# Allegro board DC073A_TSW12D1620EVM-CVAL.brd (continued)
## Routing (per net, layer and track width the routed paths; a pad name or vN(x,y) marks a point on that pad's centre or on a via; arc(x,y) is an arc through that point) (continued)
N21623803: length 2.1
  BOTTOM w0.152: U12.52 30.7,37.88 R192.1
N21623805: length 2.7
  BOTTOM w0.152: R191.1 28.54,37.85 29.7,39 U12.54
N21623807: length 3.2
  BOTTOM w0.152: U12.48 36.26,41.84 R193.1
N21623845: length 2.4
  BOTTOM w0.152: R155.1 30.2,38.45 U12.53
N21637810:
  vias: v2(14.61,98.55)
N21637823: length 2
  BOTTOM w0.254: U20.1 16.19,99.12 R188.1
N21637881: length 39.5
  L10_SIG3 w0.127: SW1.2 6.68,131.5 10.29,127.89 10.29,124.28 10.76,123.81 10.76,111.87 10.36,111.48 10.36,101.32 12.19,99.49 v1(15.44,99.49)
  BOTTOM w0.152: v1(15.44,99.49) 15.69,99.74 U20.2
N21638540: length 10.1
  BOTTOM w0.152: U20.9 12.19,94.04 J35.1
N21638545: length 80
  TOP w0.305: v1(23.57,90.3) 18.47,90.3 J35.2 17.42,95.35 TP17.1
  BOTTOM w0.305: v1(23.57,90.3) 28.13,90.3 28.15,90.32 28.59,90.32 28.62,90.3 28.65,90.3 39.67,79.27 39.67,78.18 42.7,75.16 47.52,75.16 49.05,73.63 62.99,73.63 63.45,73.18 67.34,73.18 70.03,70.48 U22.2
N21638708: length 18.2
  BOTTOM w0.152: JP13.1 11.19,87.24 U20.11
N21638717: length 14
  BOTTOM w0.152: U20.10 11.69,90.68 JP12.1
N21648189: length 11.6
  BOTTOM w0.305: TP18.1 25.73,88.72 25.43,89.03 U21.1 18.72,89.03 JP12.2
N21648194: length 78.4
  BOTTOM w0.305: JP13.2 17.3,83.54 19.1,81.74 29.77,81.74 38.43,73.08 47.27,73.08 48.74,71.6 52.81,71.6 55.78,68.63 59.13,68.63 62.23,71.73 67.08,71.73 69.55,69.27 84.07,69.27 84.12,69.22 TP19.1
N21648707: length 5
  TOP w0.305: 16.71,100.94 16.71,100.74 v2(16.92,100.53) 17.07,100.69 17.39,100.69 17.65,100.95 17.65,101.02 v4(17.86,101.02) ; 16.71,100.94 17.78,100.94 v4(17.86,101.02) ; 16.71,100.94 v4(16.71,101.14) v4(17.2,101.14) 17.73,101.14 v4(17.86,101.02)
  BOTTOM w0.305: v4(17.2,101.14) 17.73,101.14 v4(17.86,101.02)
N21648712: length 3.5
  TOP w0.305: v4(17.86,101.63) 17.83,101.65 v4(17.2,101.65) v4(16.71,101.65) ; v4(17.22,103.15) 17.07,103 R186.2 16.87,103 v4(16.71,103.15)
  BOTTOM w0.305: v4(17.86,101.63) 17.22,101.63 v4(17.2,101.65)
  BOTTOM w0.508: v2(19.43,102.95) v2(19.43,101.91)
N21649143: length 7
  BOTTOM w0.305: U20.46 18.01,102.14 19.25,100.89 C231.1 19.97,100.89 22.31,103.23 Y3.1
N21649147: length 6.9
  BOTTOM w0.305: U20.45 17.9,102.64 19.23,103.96 C232.1 19.46,103.96 20.41,103.01 20.84,103.01 21.96,104.13 Y3.2
N21650021: length 8.3
  TOP w0.381: Y4.2 24.08,106.35 C235.1 20.4,106.35 19.96,105.92 18.54,105.92 v4(16.76,104.14)
N21650025: length 8.5
  TOP w0.381: v4(16.99,103.66) 17.45,103.66 18.47,102.64 18.47,102.03 19.28,101.22 C234.1 24.08,101.22 Y4.1
N21650057: length 6.8
  TOP w0.381: C234.2 20.7,102.26 v1(20.7,104.62) C235.2
  BOTTOM w0.305: U20.41 20.51,104.64 v1(20.7,104.62)
N216554902: length 20.8
  L05_SIG1 w0.127: v2(13.67,24.36) v2(12.83,24.36) 11.61,24.36 6.22,29.74 v2(4.78,29.74) v2(4.78,28.68) 4.78,20.07 v2(4.75,20.04)
  vias: v2(3.71,30.76) v2(3.71,29.74) v2(3.71,28.68) v2(3.68,20.04) v2(3.68,19.02) v2(3.68,17.96) v2(4.75,19.02) v2(4.75,17.96) v2(4.78,30.76) v2(5.84,30.71) v2(5.84,29.72) v2(5.84,28.7) v2(5.82,19.99) v2(5.82,19) v2(5.82,17.98) v2(14.48,24.36)

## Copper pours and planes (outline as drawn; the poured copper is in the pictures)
1V9A on TOP, BOTTOM: 71.75,46.35 71.75,49.15 74.55,49.15 74.55,46.35
1V9A on L03_PWR: 69.85,78.61 71.12,79.88 71.37,79.88 71.63,79.63 71.63,78.74 72.39,77.98 75.18,77.98 76.2,78.99 76.2,80.77 74.8,82.17 74.8,88.52 75.06,88.77 75.56,88.77 76.07,89.28 76.07,90.3 75.29,91.08 72.03,91.08 71.75,90.81 70.74,90.81 70.74,97.92 77.47,97.92 79.12,96.27 79.12,94.87 80.14,93.85 81.41,93.85 81.53,93.73 81.53,91.82 80.9,91.19 80.9,80.01 81.53,79.38 81.53,76.96 81.41,76.83 79.25,76.83 77.98,75.56 77.98,73.03 76.83,71.88 76.83,45.97 69.85,45.97
1V9DR on TOP, BOTTOM: 85.98,46.1 85.98,48.9 89.92,48.9 89.92,46.1
1V9DR on L03_PWR: 83.29,46.1 83.29,72.77 83.87,73.36 83.87,75.34 83.82,75.39 83.82,77.34 84.61,78.13 84.61,92.68 83.82,93.47 83.82,97.92 96.42,97.92 96.42,46.1
1V9E on TOP, BOTTOM: 78.23,46.23 78.23,48.9 80.9,48.9 80.9,46.23
1V9E on L03_PWR: 77.6,46.23 77.6,71.63 79.63,73.66 79.63,75.56 80.39,76.33 81.41,76.33 81.69,76.61 81.69,93.95 81.41,94.23 80.39,94.23 79.63,95 79.63,97.92 83.44,97.92 83.44,93.47 83.95,92.96 83.95,78.49 83.57,78.11 83.57,73.53 81.28,71.25 81.28,46.23
1V9TC on TOP, BOTTOM: 65.02,46.35 65.02,49.02 67.56,49.02 67.56,46.35
1V9TC on L03_PWR: 72.01,79.88 71.5,80.39 70.74,80.39 69.24,78.89 69.24,45.97 59.99,45.97 59.99,63.32 57.07,66.24 57.07,81.46 65.91,90.3 75.31,90.3 75.31,89.15 74.68,89.15 74.3,88.77 74.3,82.04 75.31,81.03 75.31,79.5 74.8,78.99 72.26,78.99 72.01,79.25 ; 1 cut-out
3.3VLMX on TOP: 5.08,75.44 5.08,79.12 6.22,79.12 6.86,79.76 6.86,81.03 12.95,81.03 15.62,78.36 15.62,75.44
3.3VLMX on BOTTOM: 13.46,114.4 13.46,111.73 21.13,111.73 21.13,114.4
3.3VLMX on BOTTOM: 9.83,75.44 9.83,78.33 15.21,78.33 15.49,78.05 15.49,75.44
3.3VLMX on L03_PWR: 16.1,75.59 8.2,75.59 8.2,114.6 21.21,114.6 21.36,114.45 21.36,109.3 18.26,109.3 16.1,107.14
4.8VLMH on TOP: 45.21,14.1 45.21,29.08 48.64,29.08 48.64,14.1
5.0V_IN on TOP: 11.18,9.53 11.18,21.97 11.56,22.35 16.1,22.35 16.64,21.82 16.64,9.53
5.0V_IN on BOTTOM: 11.18,9.53 11.18,22.35 16.64,22.35 16.64,9.53
5VIN on TOP: 2.54,65.02 2.54,57.53 6.86,57.53 6.86,65.02
5VIN on TOP: 35.05,1.52 35.05,5.33 47.12,5.33 47.12,1.52
5VIN on TOP: 50.93,1.52 50.93,5.97 52.2,5.97 52.2,4.7 56.77,4.7 56.9,4.83 56.9,6.48 56.64,6.73 56.64,9.78 59.82,9.78 59.82,1.52
5VIN on TOP, BOTTOM: 28.96,10.29 33.66,10.29 33.66,19.3 30.86,19.3 30.86,16.51 28.96,16.51
5VIN on BOTTOM: 101.6,3.94 101.6,8.13 100.08,9.65 100.08,13.34 98.93,13.34 98.93,3.94
5VIN on BOTTOM: 56.9,1.52 56.9,6.71 59.82,6.71 59.82,1.52
5VIN on BOTTOM: 35.26,2.06 35.26,5.33 41.4,5.33 41.4,2.06
5VIN on L03_PWR, L08_SIG2: 14.1,63.75 14.1,16.76 19.81,11.05 28.07,11.05 28.7,11.68 28.7,19.3 36.32,19.3 36.32,7.24 36.96,6.6 87.76,6.6 90.93,9.78 104.27,9.78 104.27,1.52 8.38,1.52 1.4,8.51 1.4,63.75
+2.2V on TOP: 69.09,1.52 69.09,24.26 74.04,24.26 74.04,4.83 81.15,4.83 81.15,7.11 85.6,7.11 85.6,1.52
+2.5V on TOP, BOTTOM: 99.97,29.39 99.97,33.53 103.45,33.53 103.45,29.39
+2.5V on L03_PWR: 88.39,111.38 84.71,111.38 79.12,116.97 79.12,122.68 80.52,124.08 104.9,124.08 109.07,119.91 109.07,26.92 98.17,26.92 98.17,101.6 ; 5 cut-outs
+3.3V_LMX on BOTTOM: 15.54,116.05 15.54,117.45 15.16,117.83 15.16,119.1 15.04,119.23 15.04,122.78 14.91,122.91 13,122.91 13,116.05
+3.3V_LMX on L03_PWR: 12.85,117.81 12.85,125.7 21.13,133.99 21.13,147.19 30.3,147.19 30.3,132.28 30.99,131.6 35.48,131.6 35.48,123.06 30.23,117.81
+4.8V_LMH on TOP: 44.2,27.3 44.2,31.22 40.26,31.22 40.26,27.3
+4.8V_LMH on BOTTOM: 44.2,27.3 44.2,30.86 40.26,30.86 40.26,27.3
+4.8V_LMH on L03_PWR: 37.36,27.56 37.36,75.69 40.74,75.69 43.51,78.46 43.51,109.98 59.08,109.98 59.08,105.21 56.44,102.57 56.44,65.79 59.08,63.14 59.08,52.32 54.38,52.32 51.05,49 51.05,27.56
GND on TOP: 0.38,152.02 111.76,152.02 111.76,114.94 149.48,114.93 149.48,47.37 111.89,47.37 111.89,0.38 0.38,0.38 ; 34 cut-outs
GND on BOTTOM: 0.38,152.02 111.76,152.02 111.76,114.94 149.48,114.93 149.48,47.37 111.89,47.37 111.89,0.38 0.38,0.38 ; 25 cut-outs
GND on L02_GND1: 0.38,152.02 111.76,152.02 111.76,114.94 149.48,114.93 149.48,47.37 111.89,47.37 111.89,0.38 0.38,0.38 ; 9 cut-outs
GND on L03_PWR: 0.38,152.02 111.76,152.02 111.76,114.94 149.48,114.93 149.48,47.37 111.89,47.37 111.89,0.38 0.38,0.38 ; 4 cut-outs
GND on L04_GND2, L06_GND3, L07_GND4, L09_GND5, L11_GND6: 0.38,152.02 111.76,152.02 111.76,114.94 149.48,114.93 149.48,47.37 111.89,47.37 111.89,0.38 0.38,0.38 ; 3 cut-outs
GND on L05_SIG1: 0.38,152.02 111.76,152.02 111.76,114.94 149.48,114.93 149.48,47.37 111.89,47.37 111.89,0.38 0.38,0.38 ; 52 cut-outs
VDDD33 on TOP: 16.56,106.5 16.56,107.82 18.19,107.82 18.19,106.5
VDDD33 on TOP: 16.61,98.22 16.61,99.75 18.24,99.75 18.24,98.22
VDDD33 on TOP, BOTTOM: 17.07,73.51 17.07,80.44 20.17,80.44 20.17,73.51
VDDD33 on L05_SIG1: 20.45,21.21 3.3,38.35 3.3,113.74 14.61,125.04 74.52,125.04 78.28,121.28 78.28,112.22 74.9,108.84 33.78,108.84 24.26,99.31 24.26,54.86 26.8,52.32 26.8,45.97 27.43,45.34 30.61,45.34 31.24,45.97 31.24,52.32 33.78,52.32 40.13,45.97 40.13,33.27 42.04,31.37 50.93,31.37 51.56,32 51.56,36.45 52.2,37.08 52.2,38.35 59.82,38.35 59.82,21.21 ; 3 cut-outs
VDDL19 on TOP: 68.55,38.68 64.57,38.68 64.57,33.32 68.55,33.32
VDDL19 on BOTTOM: 68.61,38.68 64.57,38.68 64.57,33.32 68.61,33.32
VDDL19 on L03_PWR: 51.94,32.13 51.94,36.45 64.26,36.45 64.64,36.83 64.64,38.61 68.58,38.61 68.58,32.13
(no net) on L08_SIG2: 0.38,152.02 111.76,152.02 111.76,114.94 149.48,114.93 149.48,47.37 111.89,47.37 111.89,0.38 0.38,0.38 ; 59 cut-outs
(no net) on L10_SIG3: 0.38,152.02 111.76,152.02 111.76,114.94 149.48,114.93 149.48,47.37 111.89,47.37 111.89,0.38 0.38,0.38 ; 86 cut-outs
1P8V_USB on TOP, BOTTOM: 32,41.45 32,38.46 32.33,38.13 32.33,36.32 33.81,36.32 33.81,39.5 33.07,40.23 33.07,41.45
1P8V_USB on L03_PWR: 32,37.36 24.61,37.36 20.45,41.53 20.45,47.88 25.53,47.88 25.53,43.43 26.8,42.16 31.72,42.16 32.51,42.95 32.51,47.9 36.32,47.9 36.32,35.81 33.55,35.81
V_BUS on TOP: 5.08,35.94 5.08,37.47 7.87,37.47 8.13,37.72 8.13,40.39 10.41,40.39 10.41,35.94
VA19 on TOP, BOTTOM: 64.39,42.19 87.63,42.19 87.63,45.34 64.39,45.34
N18123409 on TOP (solid shape): 27.96,12.97 24.15,12.97 24.15,17.49 27.96,17.49
N18123409 on TOP: 19.18,1.52 19.18,21.69 14.73,26.14 12.62,26.14 12.62,31.5 19.05,31.5 26.67,23.87 28.07,20.93 28.07,1.52
N18123409 on BOTTOM: 19.18,1.52 19.18,21.21 27.43,21.21 28.07,20.57 28.07,1.52
N20772352 on TOP: 67.69,24.38 67.69,21.46 57.91,21.46 57.91,24.38
N20774965 on TOP: 78.74,11.81 78.74,8 84.58,8 84.58,11.81
N20775020 on TOP: 80.01,28.19 80.01,29.59 79.38,30.23 74.42,30.23 74.42,32.89 83.82,32.89 84.96,31.75 95.76,31.75 95.76,26.16 88.9,26.16 88.9,26.67 88.77,26.8 84.71,26.8 84.45,26.54 84.45,24.89 80.14,24.89 80.14,28.07
N20775144 on TOP: 77.47,24.89 77.47,29.59 79.12,29.59 79.5,29.21 79.5,28.19 78.49,28.19 78.49,24.89
N20776453 on TOP, BOTTOM: 70.92,31.24 70.92,37.47 73.08,39.62 80.98,39.62 80.98,35.94 75.44,35.94 73.79,34.29 73.79,31.24
N20776453 on L03_PWR: 70.92,31.24 70.92,37.47 73.08,39.62 80.98,39.62 80.98,35.94 75.44,35.94 73.94,34.44 73.94,31.24
N21435177 on TOP: 73.53,30.48 73.53,27.69 70.48,27.69 70.48,30.48
N21435177 on TOP: 80.52,7.49 80.52,5.33 75.82,5.33 75.82,7.49
N21435177 on BOTTOM: 70.36,8.76 70.36,30.48 74.17,30.48 74.17,10.67 76.71,8.13 80.52,8.13 80.52,4.57 74.55,4.57
N21453692 on TOP: 99.69,27.69 99.69,21.72 101.98,21.72 101.98,27.69
N21453692 on BOTTOM: 100.33,27.69 100.33,21.72 101.6,21.72 101.6,27.69
N21648707 on TOP: 16.54,101.3 16.54,100.28 18.03,100.28 18.03,101.3
N21648707 on BOTTOM: 16.46,101.32 16.46,100.23 18.01,100.23 18.01,101.32
N21648712 on L03_PWR: 16.51,103.33 16.51,101.45 19.33,101.45 19.68,101.8 19.68,103.05 19.41,103.33
N216554902 on TOP: 3.28,20.78 3.28,17.22 6.2,17.22 6.2,20.78
N216554902 on TOP: 3.3,31.5 3.3,27.94 6.22,27.94 6.22,31.5

Small or netless copper shapes (teardrops, artwork), in the pictures only: 6 on L11_GND6

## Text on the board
BOTTOM: LAYER 12 (BOTTOM SIDE)
Board Geometry/Soldermask Bottom: SOLDERMASK BOTTOM
Ref Des/Silkscreen Bottom: GND | SILKSCREEN BOTTOM
User.Comments: C118 | C119 | C117 | C78 | C79 | C81 | C115 | C88 | C73 | C75 | C67 | C68 | C76 | C86 | C125 | C38 | C39 | C69 | C70 | C71 | C74 | C63 | C65 | C66 | C126 | C114 | C87 | C64 | C85 | C84 | C83 | C82 | C124 | Y2 | U8 | U17 | C56 | C103 | C111 | U22 | C206 | C207 | R55 | R54 | C48 | C109 | C105 | C104 | R35 | R38 | R56 | R57 | C49 | C100 | C122 | C121 | C120 | R40 | C93 | C92 | R117 | R121 | R129 | R131 | C90 | C80 | R51 | C91 | C72 | C89 | R116 | R120 | R128 | R130 | T1 | U9 | C156 | R125 | R123 | R124 | R122 | R139 | R144 | R156 | R153 | R159 | R193 | R143 | R142 | R138 | R150 | R149 | R141 | C131 | R151 | R95 | C134 | R90 | U21 | R147 | R146 | R157 | R145 | C140 | R93 | U14 | U12 | C136 | D9 | U7 | Y3 | U13 | R96 | FB9 | R91 | C212 | C211 | FB7 | C220 | C219 | C218 | C221 | U20 | U10 | R89 | R137 | R135 | C150 | C130 | R188 | J32 | C102 | R44 | C40 | C43 | R28 | A40 | J28 | K40 | C51 | C55 | C44 | C52 | C101 | C45 | C50 | C46 | C112 | C47 | C99 | C110 | C108 | R174 | R87 | C97 | C98 | C106 | C107 | C95 | C94 | R86 | C116 | R46 | R42 | R85 | R32 | R29 | R33 | R30 | R88 | C144 | C138 | R94 | C132 | R185 | R107 | R184 | R105 | C162 | R92 | R192 | R155 | C135 | R191 | C128 | Y1 | C223 | R102 | C222 | C153 | C133 | R110 | C129 | R111 | C127 | C231 | C232 | C175 | C174 | FB8 | R132 | C238 | R190 | A1 | A21 | A36 | K1 | K21 | K36 | * | BOARD EDGE | C41 | C42 | R53 | R13 | TEXAS INSTRUMENTS, INC. | TSW12D1620CVAL EVM REV A | DC073 | SEE NOTE 16
TOP: LAYER 1 (TOP SIDE)
Board Geometry/Soldermask Top: SOLDERMASK TOP
Ref Des/Silkscreen Top: STAT | BUFFER | EXT | TCK | TMS | TDO | TDI | ON | SILKSCREEN TOP | DC073A
L02_GND1: LAYER 2 - GND
L03_PWR: LAYER 3 - PWR
L04_GND2: LAYER 4 - GND
L05_SIG1: LAYER 5 - SIG1
L06_GND3: LAYER 6 - GND
L07_GND4: LAYER 7 - GND
L08_SIG2: LAYER 8 - SIG2
L09_GND5: LAYER 9 - GND
L10_SIG3: LAYER 10 - SIG3
L11_GND6: LAYER 11 - GND
COMPVAL_TYPE_TOP: PASTEMASK TOP
TOLERANCE_TOP: PASTEMASK BOTTOM
USER_PART_NUM_TOP: TOP VIEW | BOTTOM VIEW
PLACE_BOUND_TOP: SOLDERMASK TOP SOCKET BOARD
PAGE_OUTLINE: PASTEMASK TOP SOCKET BOARD
User.14: 06-08-18 | 3. MARK BOARD'S SILKSCREEN WITH THE APPROPRIATE EVM PART NUMBER AND SERIAL NUMBER. | 4. IPC-A-610 / ACCEPTABILITY OF ELECTRONIC ASSEMBLIES, CLASS2, CURRENT REVISION. | DC073
User.26: FIGURE | SIZE | 6.0 | 8.0 | 10.0 | 12.0 | 15.0 | 36.0 | 38.0 | 40.0 | 55.0 | 59.0 | 63.0 | 106.0 | 120.0 | 125.0 | 140.0 | 35.0 | 50.0 | DRILL CHART: TOP to BOTTOM | ALL UNITS ARE IN MILS | PLATED | NON-PLATED | QTY | 387 | 1383 | 2337 | 37 | 25 | 128 | 14 | 2 | 30 | 50 | 4 | 72 | 1
